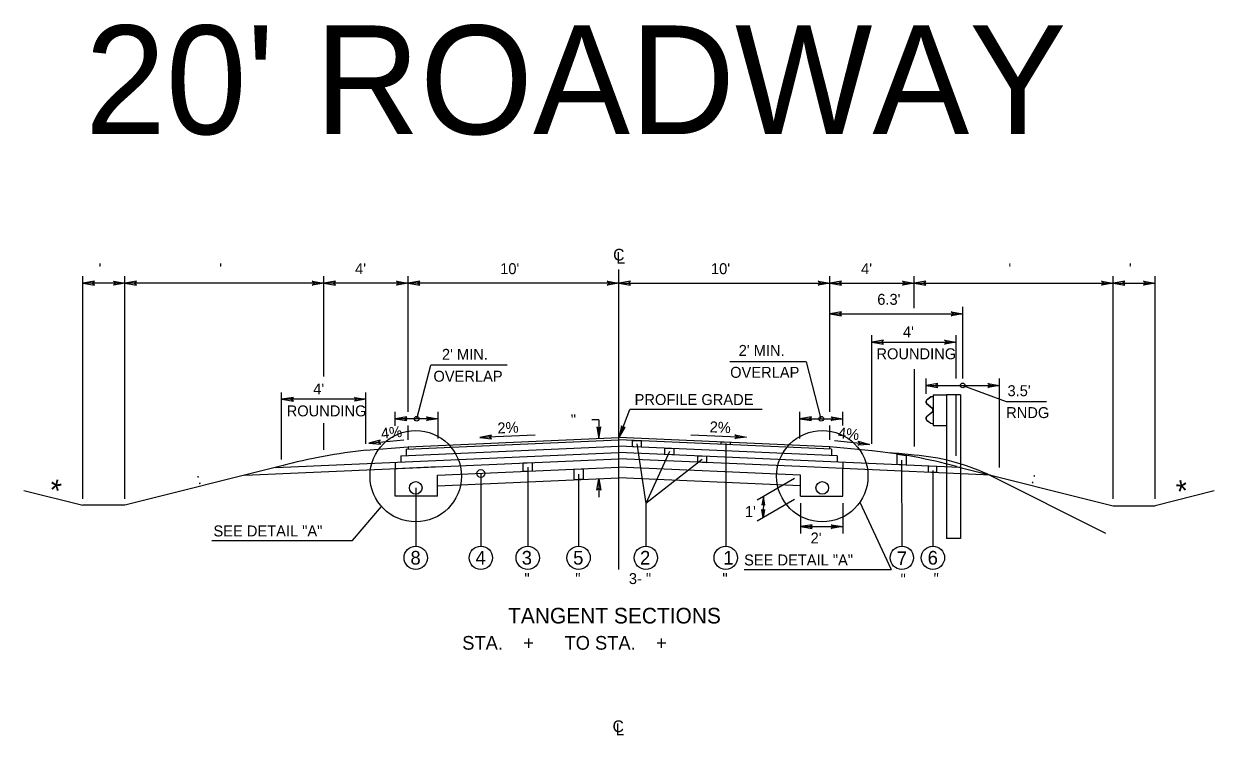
# Model space of a CAD drawing. Extents: x -540 to 1231, y -564 to 421.
# Drawn here: x -349.4 to -197.3, y 224.3 to 315.3 of the extents above; entities that cross this region are included whole.
import ezdxf

# ---------------------------------------------------------------- set-up
doc = ezdxf.new("R2010")
doc.units = 0
doc.layers.add('1', color=7, linetype='Continuous')
doc.layers.add('Des_ Drain_ Ftrs', color=7, linetype='Continuous')

msp = doc.modelspace()

# ---------------------------------------------------------------- linework, layer by layer
at = {"layer": '1'}
for p, q in [((-341.89, 254.57), (-341.89, 283.02)), ((-336.51, 254.57), (-336.51, 283.02)), ((-311.1, 270.19), (-311.1, 283.02)), ((-300.32, 265.69), (-300.32, 283.02)), ((-273.38, 245.55), (-273.38, 283.9)), ((-246.44, 265.69), (-246.44, 283.02)), ((-235.66, 278.96), (-235.66, 283.02)), ((-210.24, 254.57), (-210.24, 283.02)), ((-204.85, 254.57), (-204.85, 283.02)), ((-336.51, 282.14), (-341.89, 282.14)), ((-311.09, 282.14), (-336.51, 282.14)), ((-300.32, 282.14), (-311.09, 282.14)), ((-273.38, 282.14), (-300.32, 282.14)), ((-273.38, 282.14), (-246.44, 282.14)), ((-246.44, 282.14), (-235.66, 282.14)), ((-235.66, 282.14), (-210.24, 282.14)), ((-210.24, 282.14), (-204.85, 282.14)), ((-229.45, 269.94), (-229.45, 279.1)), ((-246.42, 278.22), (-229.45, 278.22)), ((-241.05, 261.59), (-241.05, 275.47)), ((-230.27, 269.94), (-230.27, 275.47)), ((-241.05, 274.59), (-230.27, 274.59)), ((-299.22, 264.81), (-297.43, 271.64)), ((-287.66, 271.64), (-297.43, 271.64)), ((-259.21, 272.14), (-249.44, 272.14)), ((-247.54, 264.81), (-249.43, 272.09)), ((-235.66, 271.13), (-235.66, 261.26)), ((-234.14, 267.99), (-234.14, 269.94)), ((-224.76, 258.58), (-224.76, 269.94)), ((-316.49, 259.58), (-316.49, 268.17)), ((-305.71, 261.59), (-305.71, 268.17)), ((-234.14, 269.06), (-224.76, 269.06)), ((-233.23, 267.88), (-233.23, 263.95)), ((-233.23, 267.88), (-231.54, 267.88)), ((-231.54, 267.88), (-231.54, 249.48)), ((-229.72, 267.88), (-231.54, 267.88)), ((-230.27, 260.07), (-230.27, 267.86)), ((-229.72, 267.88), (-229.72, 249.48)), ((-229.45, 269.06), (-223.89, 266.99)), ((-305.71, 267.29), (-316.48, 267.29)), ((-234.07, 266.77), (-233.34, 266.14)), ((-233.54, 267.59), (-234.06, 267.2)), ((-234.06, 266.79), (-233.32, 266.16)), ((-233.53, 267.57), (-234.04, 267.18)), ((-233.23, 267.65), (-233.54, 267.59)), ((-233.23, 267.62), (-233.53, 267.57)), ((-223.89, 266.99), (-218.74, 266.99)), ((-301.96, 263.91), (-301.96, 265.69)), ((-296.47, 264.81), (-301.96, 264.81)), ((-296.47, 262.28), (-296.47, 265.69)), ((-273.37, 262.41), (-271.99, 265.98)), ((-255.07, 265.98), (-271.99, 265.98)), ((-250.28, 262.28), (-250.28, 265.69)), ((-250.28, 264.81), (-244.79, 264.81)), ((-244.79, 263.94), (-244.79, 265.69)), ((-233.34, 265.69), (-234.07, 265.05)), ((-233.32, 265.66), (-234.06, 265.03)), ((-233.26, 265.95), (-233.26, 265.87)), ((-233.23, 265.95), (-233.23, 265.87)), ((-311.1, 260.81), (-311.1, 264.22)), ((-300.32, 262.11), (-300.32, 263.93)), ((-275.96, 264.66), (-276.84, 264.66)), ((-275.96, 264.66), (-275.96, 262.3)), ((-246.44, 262.11), (-246.44, 263.93)), ((-234.06, 264.62), (-233.54, 264.23)), ((-234.04, 264.64), (-233.53, 264.26)), ((-233.54, 264.23), (-233.23, 264.17)), ((-233.53, 264.26), (-233.23, 264.2)), ((-233.23, 263.95), (-231.54, 263.95)), ((-305.34, 261.67), (-300.86, 262.11)), ((-300.56, 260.92), (-273.38, 262.11)), ((-300.32, 261.23), (-273.38, 262.41)), ((-284.07, 262.71), (-291.15, 262.4)), ((-246.43, 261.23), (-273.38, 262.41)), ((-246.2, 260.92), (-273.38, 262.11)), ((-264.18, 262.76), (-257.09, 262.45)), ((-259.74, 261.65), (-259.74, 248.52)), ((-241.35, 261.53), (-245.83, 261.97)), ((-317.25, 258.58), (-273.38, 260.49)), ((-305.71, 260.78), (-300.32, 261.23)), ((-301.26, 260.08), (-273.38, 261.3)), ((-300.56, 260.92), (-300.56, 260.12)), ((-300.32, 261.23), (-300.32, 260.93)), ((-245.49, 260.08), (-273.38, 261.3)), ((-229.85, 258.59), (-273.38, 260.49)), ((-271.1, 261.61), (-269.94, 253.98)), ((-266.93, 260.62), (-269.94, 253.98)), ((-246.44, 260.93), (-246.44, 261.23)), ((-241.05, 260.71), (-246.43, 261.23)), ((-246.2, 260.92), (-246.2, 260.12)), ((-316.48, 258.77), (-336.51, 253.76)), ((-321.18, 257.6), (-273.38, 259.68)), ((-301.96, 259.24), (-301.96, 258.44)), ((-301.96, 258.44), (-296.48, 258.68)), ((-301.26, 260.08), (-301.26, 259.28)), ((-296.58, 257.59), (-273.38, 258.61)), ((-285.04, 258.63), (-285.04, 248.52)), ((-250.27, 258.68), (-273.38, 259.68)), ((-250.18, 257.59), (-273.38, 258.61)), ((-262.75, 259.61), (-269.94, 253.98)), ((-244.79, 258.44), (-250.27, 258.68)), ((-245.49, 260.08), (-245.49, 259.28)), ((-244.79, 259.24), (-244.79, 258.44)), ((-237.26, 259.49), (-237.23, 248.51)), ((-234.14, 259.93), (-234.14, 259.93)), ((-230.27, 258.7), (-210.24, 253.69)), ((-301.96, 254.9), (-301.96, 258.44)), ((-296.58, 254.9), (-296.58, 257.59)), ((-296.58, 256.24), (-273.38, 257.26)), ((-291.03, 257.81), (-291.03, 248.52)), ((-278.54, 257.71), (-278.54, 248.52)), ((-275.96, 257.14), (-275.96, 254.78)), ((-250.18, 256.24), (-273.38, 257.26)), ((-250.94, 257.15), (-255.7, 254.4)), ((-250.18, 254.9), (-250.18, 257.59)), ((-250.18, 257.59), (-250.18, 257.59)), ((-244.79, 254.9), (-244.79, 258.44)), ((-225.92, 257.61), (-244.79, 258.44)), ((-233.26, 258.21), (-233.26, 248.52)), ((-226.26, 257.7), (-211.2, 250.17)), ((-349.43, 255.65), (-341.9, 253.76)), ((-299.35, 255.97), (-299.35, 248.52)), ((-197.32, 255.57), (-204.85, 253.69)), ((-296.58, 254.9), (-301.96, 254.9)), ((-250.94, 254.46), (-255.71, 251.7)), ((-254.93, 254.84), (-254.96, 252.14)), ((-250.18, 254.9), (-244.79, 254.9)), ((-242.59, 254.14), (-238.61, 245.55)), ((-336.51, 253.76), (-341.9, 253.76)), ((-307.45, 249.25), (-303.71, 253.57)), ((-269.94, 253.98), (-269.94, 248.52)), ((-250.18, 254.02), (-250.18, 250.13)), ((-244.79, 254.02), (-244.79, 250.13)), ((-210.24, 253.69), (-204.85, 253.69)), ((-250.18, 251.01), (-244.79, 251.01)), ((-229.72, 249.48), (-231.54, 249.48)), ((-325.39, 249.25), (-307.45, 249.25)), ((-257.4, 245.55), (-238.61, 245.55))]:
    msp.add_line(p, q, dxfattribs=at)
for points in [[(-271.67, 262.04), (-270.53, 261.99), (-270.53, 261.18), (-271.67, 261.23)], [(-260.31, 261.84), (-259.17, 261.79), (-259.17, 261.49), (-260.31, 261.54)], [(-267.5, 261.05), (-266.35, 261), (-266.35, 260.19), (-267.5, 260.24)], [(-236.67, 258.89), (-237.81, 258.94), (-237.81, 260.29), (-236.67, 260.11)], [(-285.61, 259.15), (-284.47, 259.2), (-284.47, 258.12), (-285.61, 258.07)], [(-263.32, 260.05), (-262.18, 260), (-262.18, 259.19), (-263.32, 259.24)], [(-233.84, 258.79), (-232.81, 258.74), (-232.81, 257.94), (-233.84, 257.98)], [(-279.11, 258.35), (-277.97, 258.4), (-277.97, 257.06), (-279.11, 257.01)]]:
    msp.add_lwpolyline(points, close=True, dxfattribs=at)
for centre, radius in [((-229.45, 269.06), 0.3), ((-299.22, 264.81), 0.3), ((-247.54, 264.81), 0.3), ((-299.35, 257.46), 5.84), ((-247.4, 257.46), 5.84), ((-291.03, 257.81), 0.5), ((-299.35, 255.97), 0.808), ((-247.4, 255.97), 0.808), ((-299.35, 247.03), 1.49), ((-291.03, 247.03), 1.49), ((-285.04, 247.03), 1.49), ((-278.54, 247.03), 1.49), ((-269.94, 247.03), 1.49), ((-259.74, 247.03), 1.49), ((-237.23, 247.03), 1.49), ((-233.26, 247.03), 1.49)]:
    msp.add_circle(centre, radius, dxfattribs=at)
for centre, radius, start, end in [((-233.89, 266.98), 0.278, 126.9799, 229.021), ((-233.89, 266.98), 0.249, 126.9799, 229.021), ((-233.89, 264.84), 0.278, 130.979, 233.0201), ((-233.89, 264.84), 0.249, 130.979, 233.0201), ((-233.51, 265.95), 0.249, 0, 49.0365), ((-233.51, 265.87), 0.249, 310.9635, 0), ((-233.51, 265.95), 0.278, 0, 49.0365), ((-233.51, 265.87), 0.278, 310.9635, 0), ((-298.82, 193.94), 67.19, 95.8795, 105.2381), ((-247.93, 193.87), 67.19, 74.7593, 84.1179), ((-246.46, 159.49), 101.24, 83.8633, 85.6775), ((-237.76, 232.87), 27.37, 65.1374, 85.5513)]:
    msp.add_arc(centre, radius, start, end, dxfattribs=at)
at = {"layer": 'Des_ Drain_ Ftrs'}
for points in [[(-341.89, 282.14), (-340.41, 281.89), (-340.7, 282.14), (-340.41, 282.38)], [(-336.51, 282.14), (-337.99, 281.89), (-337.7, 282.14), (-337.99, 282.38)], [(-336.51, 282.14), (-335.02, 281.89), (-335.31, 282.14), (-335.02, 282.38)], [(-311.09, 282.14), (-312.58, 281.89), (-312.29, 282.14), (-312.58, 282.38)], [(-311.09, 282.14), (-309.61, 281.89), (-309.9, 282.14), (-309.61, 282.38)], [(-300.32, 282.14), (-301.81, 281.89), (-301.51, 282.14), (-301.81, 282.38)], [(-300.32, 282.14), (-298.83, 281.89), (-299.12, 282.14), (-298.83, 282.38)], [(-273.38, 282.14), (-274.87, 281.89), (-274.57, 282.14), (-274.87, 282.38)], [(-273.38, 282.14), (-271.89, 281.89), (-272.18, 282.14), (-271.89, 282.38)], [(-246.44, 282.14), (-247.92, 281.89), (-247.63, 282.14), (-247.92, 282.38)], [(-246.44, 282.14), (-244.95, 281.89), (-245.24, 282.14), (-244.95, 282.38)], [(-235.66, 282.14), (-237.15, 281.89), (-236.85, 282.14), (-237.15, 282.38)], [(-235.66, 282.14), (-234.17, 281.89), (-234.47, 282.14), (-234.17, 282.38)], [(-210.24, 282.14), (-211.73, 281.89), (-211.43, 282.14), (-211.73, 282.38)], [(-210.24, 282.14), (-208.75, 281.89), (-209.05, 282.14), (-208.75, 282.38)], [(-204.85, 282.14), (-206.34, 281.89), (-206.05, 282.14), (-206.34, 282.38)], [(-246.42, 278.22), (-244.93, 277.97), (-245.23, 278.22), (-244.93, 278.47)], [(-229.45, 278.22), (-230.94, 277.97), (-230.64, 278.22), (-230.94, 278.47)], [(-241.05, 274.59), (-239.56, 274.34), (-239.85, 274.59), (-239.56, 274.84)], [(-230.27, 274.59), (-231.76, 274.34), (-231.46, 274.59), (-231.76, 274.84)], [(-234.14, 269.06), (-232.65, 268.81), (-232.95, 269.06), (-232.65, 269.31)], [(-224.76, 269.06), (-226.24, 268.81), (-225.95, 269.06), (-226.24, 269.31)], [(-316.48, 267.29), (-314.99, 267.05), (-315.29, 267.29), (-314.99, 267.54)], [(-305.71, 267.29), (-307.19, 267.05), (-306.9, 267.29), (-307.19, 267.54)], [(-301.96, 264.81), (-300.47, 264.56), (-300.77, 264.81), (-300.47, 265.06)], [(-296.47, 264.81), (-297.96, 264.56), (-297.67, 264.81), (-297.96, 265.06)], [(-250.28, 264.81), (-248.79, 264.56), (-249.09, 264.81), (-248.79, 265.06)], [(-244.79, 264.81), (-246.28, 264.56), (-245.99, 264.81), (-246.28, 265.06)], [(-275.96, 262.3), (-275.71, 263.78), (-275.96, 263.49), (-276.21, 263.78)], [(-273.37, 262.41), (-272.6, 263.71), (-272.94, 263.52), (-273.07, 263.88)], [(-305.34, 261.67), (-303.83, 261.56), (-304.15, 261.78), (-303.88, 262.06)], [(-291.15, 262.4), (-289.66, 262.22), (-289.96, 262.45), (-289.68, 262.71)], [(-257.09, 262.45), (-258.59, 262.27), (-258.28, 262.51), (-258.57, 262.77)], [(-241.35, 261.53), (-242.86, 261.42), (-242.54, 261.64), (-242.81, 261.92)], [(-275.96, 257.14), (-275.71, 255.66), (-275.96, 255.95), (-276.21, 255.66)], [(-254.93, 254.84), (-255.12, 253.76), (-254.94, 253.98), (-254.76, 253.76)], [(-254.96, 252.14), (-255.13, 253.22), (-254.95, 253.01), (-254.77, 253.22)], [(-250.18, 251.01), (-248.69, 250.76), (-248.98, 251.01), (-248.69, 251.26)], [(-244.79, 251.01), (-246.28, 250.76), (-245.98, 251.01), (-246.28, 251.26)]]:
    msp.add_lwpolyline(points, close=True, dxfattribs=at)

# ---------------------------------------------------------------- texts
at = {"layer": '1'}
for s, height, p in [("20' ROADWAY", 13.8979, (-341.62, 301.19)), (" '", 1.4, (-340.4, 283.29)), ("  '", 1.4, (-325.5, 283.29)), ("4'", 1.4, (-307.1, 283.29)), ("10'", 1.4, (-288.56, 283.29)), ("10'", 1.4, (-261.62, 283.29)), ("4'", 1.4, (-242.44, 283.29)), ("  '", 1.4, (-224.65, 283.29)), (" '", 1.4, (-208.74, 283.29)), ("6.3'", 1.4, (-240.37, 279.37)), ("4'", 1.4, (-237.09, 275.21)), ("2' MIN.", 1.4, (-258.08, 272.84)), ('ROUNDING', 1.4, (-240.48, 272.41)), ("2' MIN.", 1.4, (-296, 272.34)), ('OVERLAP', 1.4, (-297.09, 269.54)), ('OVERLAP', 1.4, (-259.17, 270.04)), ("4'", 1.4, (-312.45, 267.91)), ('PROFILE GRADE', 1.4, (-271.38, 266.56)), ("3.5'", 1.4, (-223.73, 267.69)), ('ROUNDING', 1.4, (-315.84, 265.11)), ('RNDG', 1.4, (-223.9, 264.89)), ('SEE DETAIL "A"', 1.4, (-325.2, 249.76)), ("2'", 1.4, (-248.89, 248.86)), ('8', 1.75, (-300.02, 246.16)), ('4', 1.75, (-291.71, 246.16)), ('3', 1.75, (-285.8, 246.16)), ('5', 1.75, (-279.23, 246.16)), ('2', 1.75, (-270.68, 246.16)), ('1', 1.75, (-260.04, 246.16)), ('SEE DETAIL "A"', 1.4, (-257.39, 246.05)), ('7', 1.75, (-237.87, 246.09)), ('6', 1.75, (-233.93, 246.16)), (' "', 1.4, (-285.98, 243.67)), (' "', 1.4, (-279.48, 243.67)), ('3- "', 1.4, (-272.12, 243.67)), (' "', 1.4, (-260.68, 243.67)), (' "', 1.4, (-237.91, 243.58)), (' "', 1.4, (-233.69, 243.67)), ('TANGENT SECTIONS', 2, (-287.55, 238.63)), ('STA.    +      TO STA.    +     ', 1.75, (-293.41, 235.28))]:
    msp.add_text(s, height=height, dxfattribs=at).set_placement(p)
for s, height, rotation, p in [('  "', 1.4, 0.1438, (-280.57, 263.96)), ('4%', 1.4, 5.9401, (-303.72, 262.21)), ('2%', 1.4, 2.624, (-288.88, 262.91)), ('2%', 1.4, 357.376, (-261.82, 263.08)), ('4%', 1.4, 354.1111, (-245.45, 262.33)), (' : ', 1.4, 14.2282, (-327.68, 256.25)), (' : ', 1.4, 345.7718, (-221.3, 256.75)), ('*', 2.8, 346.0084, (-346.51, 254.48)), ('*', 2.8, 12.8479, (-201.75, 254.05)), ("1'", 1.4, 0.1438, (-257.28, 252.23))]:
    msp.add_text(s, height=height, rotation=rotation, dxfattribs=at).set_placement(p)
at = {"layer": 'Des_ Drain_ Ftrs'}
for s, p in [('C', (-274.12, 285.03)), ('L', (-273.72, 284.64)), ('C', (-274.2, 224.74)), ('L', (-273.81, 224.35))]:
    msp.add_text(s, height=1.5, dxfattribs=at).set_placement(p)

doc.saveas('drawing.dxf')
